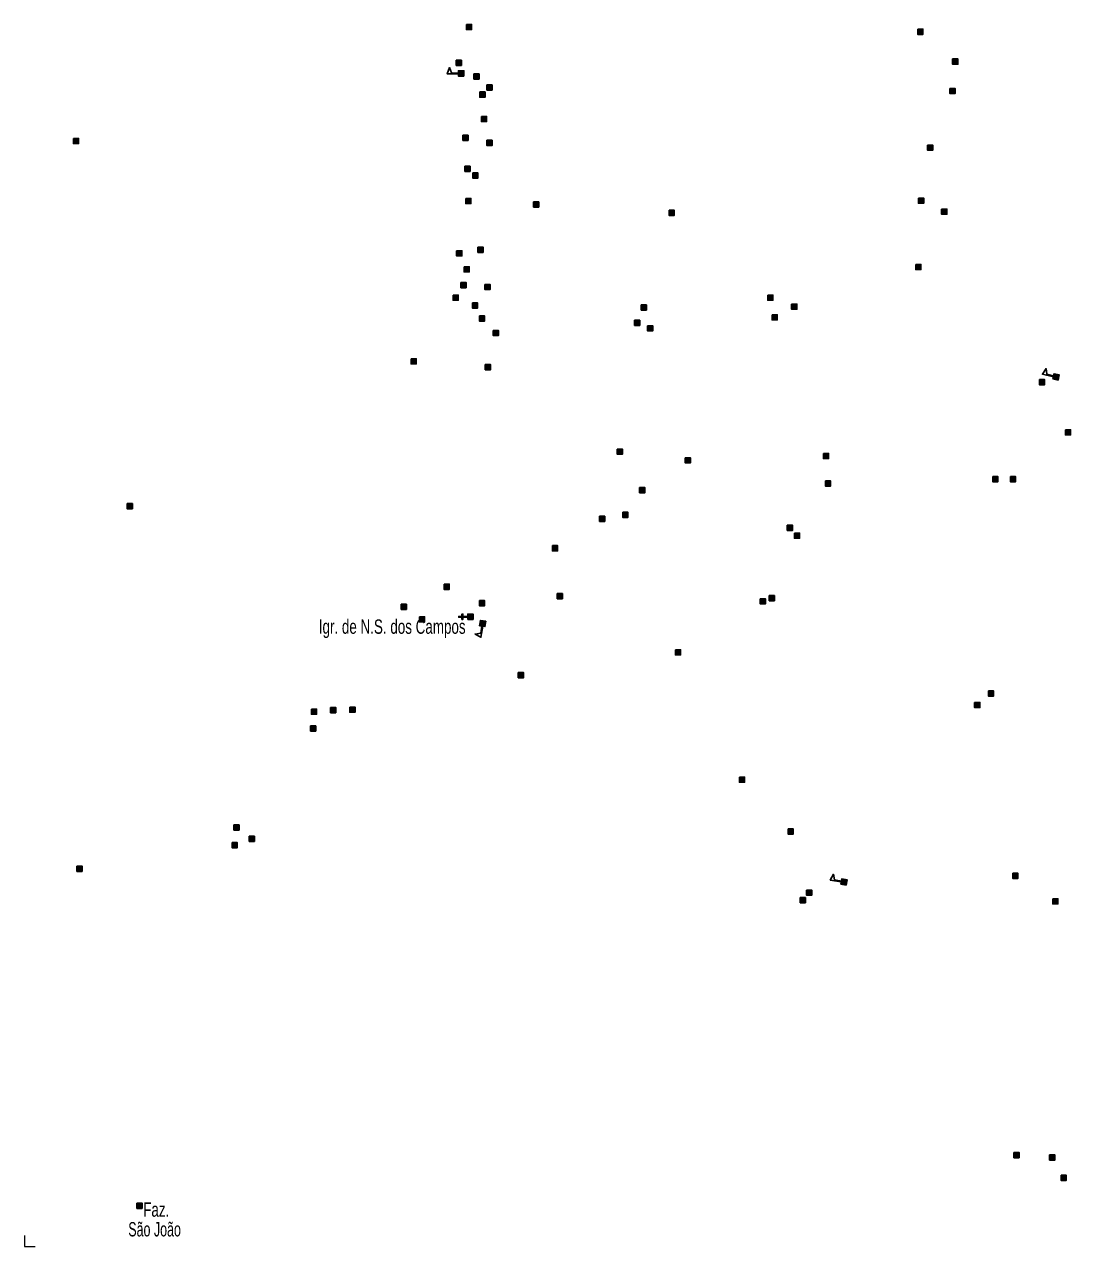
# Model space of a CAD drawing. Extents: x 647.8 to 672.9, y 6929.3 to 6957.3.
# Drawn here: x 647.83 to 653.68, y 6929.58 to 6936.4 of the extents above; entities that cross this region are included whole.
import ezdxf
from ezdxf.enums import TextEntityAlignment as Align

# ---------------------------------------------------------------- set-up
doc = ezdxf.new("R2010")
doc.units = 0
doc.header["$LTSCALE"] = 0.032
for name, color, linetype, lineweight in [('2', 7, 'Continuous', 25), ('4', 7, 'Continuous', 25), ('6', 7, 'Continuous', 25), ('63', 7, 'Continuous', 13)]:
    doc.layers.add(name, color=color, linetype=linetype, lineweight=lineweight)
doc.layers.add('61', color=7, linetype='Continuous')

msp = doc.modelspace()

# ---------------------------------------------------------------- hatches: boundary and pattern name
at = {"layer": '2'}
for points in [[(650.3009, 6936.4039), (650.3299, 6936.4039), (650.3299, 6936.3749), (650.3009, 6936.3749)], [(652.8216, 6936.3776), (652.8506, 6936.3776), (652.8506, 6936.3486), (652.8216, 6936.3486)], [(653.0169, 6936.2109), (653.0459, 6936.2109), (653.0459, 6936.1819), (653.0169, 6936.1819)], [(650.244, 6936.2043), (650.273, 6936.2043), (650.273, 6936.1753), (650.244, 6936.1753)], [(650.3426, 6936.1275), (650.3716, 6936.1275), (650.3716, 6936.0985), (650.3426, 6936.0985)], [(650.3755, 6936.0266), (650.4045, 6936.0266), (650.4045, 6935.9976), (650.3755, 6935.9976)], [(650.415, 6936.0661), (650.444, 6936.0661), (650.444, 6936.0371), (650.415, 6936.0371)], [(653.0015, 6936.0463), (653.0305, 6936.0463), (653.0305, 6936.0173), (653.0015, 6936.0173)], [(650.3842, 6935.8906), (650.4132, 6935.8906), (650.4132, 6935.8616), (650.3842, 6935.8616)], [(648.1048, 6935.7677), (648.1338, 6935.7677), (648.1338, 6935.7387), (648.1048, 6935.7387)], [(650.2811, 6935.7853), (650.3101, 6935.7853), (650.3101, 6935.7563), (650.2811, 6935.7563)], [(650.415, 6935.7567), (650.444, 6935.7567), (650.444, 6935.7277), (650.415, 6935.7277)], [(652.8764, 6935.7304), (652.9054, 6935.7304), (652.9054, 6935.7014), (652.8764, 6935.7014)], [(650.2921, 6935.612), (650.3211, 6935.612), (650.3211, 6935.583), (650.2921, 6935.583)], [(650.336, 6935.5747), (650.365, 6935.5747), (650.365, 6935.5457), (650.336, 6935.5457)], [(650.2965, 6935.4321), (650.3255, 6935.4321), (650.3255, 6935.4031), (650.2965, 6935.4031)], [(650.676, 6935.4123), (650.705, 6935.4123), (650.705, 6935.3833), (650.676, 6935.3833)], [(652.826, 6935.4343), (652.855, 6935.4343), (652.855, 6935.4053), (652.826, 6935.4053)], [(651.4329, 6935.3662), (651.4619, 6935.3662), (651.4619, 6935.3372), (651.4329, 6935.3372)], [(652.9554, 6935.3728), (652.9844, 6935.3728), (652.9844, 6935.3438), (652.9554, 6935.3438)], [(650.246, 6935.1403), (650.275, 6935.1403), (650.275, 6935.1113), (650.246, 6935.1113)], [(650.3645, 6935.16), (650.3935, 6935.16), (650.3935, 6935.131), (650.3645, 6935.131)], [(650.2877, 6935.0503), (650.3167, 6935.0503), (650.3167, 6935.0213), (650.2877, 6935.0213)], [(652.8106, 6935.0635), (652.8396, 6935.0635), (652.8396, 6935.0345), (652.8106, 6935.0345)], [(650.2702, 6934.9626), (650.2992, 6934.9626), (650.2992, 6934.9336), (650.2702, 6934.9336)], [(650.404, 6934.9516), (650.433, 6934.9516), (650.433, 6934.9226), (650.404, 6934.9226)], [(650.2263, 6934.8924), (650.2553, 6934.8924), (650.2553, 6934.8634), (650.2263, 6934.8634)], [(650.3338, 6934.8485), (650.3628, 6934.8485), (650.3628, 6934.8195), (650.3338, 6934.8195)], [(651.9835, 6934.8924), (652.0125, 6934.8924), (652.0125, 6934.8634), (651.9835, 6934.8634)], [(652.1174, 6934.8419), (652.1464, 6934.8419), (652.1464, 6934.8129), (652.1174, 6934.8129)], [(650.3733, 6934.7761), (650.4023, 6934.7761), (650.4023, 6934.7471), (650.3733, 6934.7471)], [(651.2771, 6934.8375), (651.3061, 6934.8375), (651.3061, 6934.8085), (651.2771, 6934.8085)], [(652.0077, 6934.7827), (652.0367, 6934.7827), (652.0367, 6934.7537), (652.0077, 6934.7537)], [(651.2398, 6934.752), (651.2688, 6934.752), (651.2688, 6934.723), (651.2398, 6934.723)], [(651.3122, 6934.7213), (651.3412, 6934.7213), (651.3412, 6934.6923), (651.3122, 6934.6923)], [(650.4501, 6934.6949), (650.4791, 6934.6949), (650.4791, 6934.6659), (650.4501, 6934.6659)], [(649.9915, 6934.537), (650.0205, 6934.537), (650.0205, 6934.508), (649.9915, 6934.508)], [(650.4062, 6934.5041), (650.4352, 6934.5041), (650.4352, 6934.4751), (650.4062, 6934.4751)], [(653.5017, 6934.4207), (653.5307, 6934.4207), (653.5307, 6934.3917), (653.5017, 6934.3917)], [(653.6465, 6934.1399), (653.6755, 6934.1399), (653.6755, 6934.1109), (653.6465, 6934.1109)], [(651.1433, 6934.0324), (651.1723, 6934.0324), (651.1723, 6934.0034), (651.1433, 6934.0034)], [(651.5228, 6933.9841), (651.5518, 6933.9841), (651.5518, 6933.9551), (651.5228, 6933.9551)], [(652.2951, 6934.0083), (652.3241, 6934.0083), (652.3241, 6933.9793), (652.2951, 6933.9793)], [(651.2684, 6933.8174), (651.2974, 6933.8174), (651.2974, 6933.7884), (651.2684, 6933.7884)], [(652.306, 6933.8547), (652.335, 6933.8547), (652.335, 6933.8257), (652.306, 6933.8257)], [(653.2406, 6933.8788), (653.2696, 6933.8788), (653.2696, 6933.8498), (653.2406, 6933.8498)], [(653.3393, 6933.8788), (653.3683, 6933.8788), (653.3683, 6933.8498), (653.3393, 6933.8498)], [(648.4054, 6933.7274), (648.4344, 6933.7274), (648.4344, 6933.6984), (648.4054, 6933.6984)], [(651.0446, 6933.6572), (651.0736, 6933.6572), (651.0736, 6933.6282), (651.0446, 6933.6282)], [(651.174, 6933.6792), (651.203, 6933.6792), (651.203, 6933.6502), (651.174, 6933.6502)], [(652.0932, 6933.6068), (652.1222, 6933.6068), (652.1222, 6933.5778), (652.0932, 6933.5778)], [(652.1327, 6933.5629), (652.1617, 6933.5629), (652.1617, 6933.5339), (652.1327, 6933.5339)], [(650.7813, 6933.4927), (650.8103, 6933.4927), (650.8103, 6933.4637), (650.7813, 6933.4637)], [(650.1758, 6933.2777), (650.2048, 6933.2777), (650.2048, 6933.2487), (650.1758, 6933.2487)], [(650.8076, 6933.2251), (650.8366, 6933.2251), (650.8366, 6933.1961), (650.8076, 6933.1961)], [(651.9923, 6933.2141), (652.0213, 6933.2141), (652.0213, 6933.1851), (651.9923, 6933.1851)], [(649.9367, 6933.1658), (649.9657, 6933.1658), (649.9657, 6933.1368), (649.9367, 6933.1368)], [(650.3733, 6933.1856), (650.4023, 6933.1856), (650.4023, 6933.1566), (650.3733, 6933.1566)], [(651.9419, 6933.1965), (651.9709, 6933.1965), (651.9709, 6933.1675), (651.9419, 6933.1675)], [(650.0376, 6933.0956), (650.0666, 6933.0956), (650.0666, 6933.0666), (650.0376, 6933.0666)], [(651.468, 6932.9113), (651.497, 6932.9113), (651.497, 6932.8823), (651.468, 6932.8823)], [(650.5905, 6932.7841), (650.6195, 6932.7841), (650.6195, 6932.7551), (650.5905, 6932.7551)], [(650.5905, 6932.7841), (650.6195, 6932.7841), (650.6195, 6932.7551), (650.5905, 6932.7551)], [(653.2165, 6932.681), (653.2455, 6932.681), (653.2455, 6932.652), (653.2165, 6932.652)], [(649.5418, 6932.5888), (649.5708, 6932.5888), (649.5708, 6932.5598), (649.5418, 6932.5598)], [(649.6493, 6932.591), (649.6783, 6932.591), (649.6783, 6932.562), (649.6493, 6932.562)], [(653.1397, 6932.6174), (653.1687, 6932.6174), (653.1687, 6932.5884), (653.1397, 6932.5884)], [(649.4343, 6932.5801), (649.4633, 6932.5801), (649.4633, 6932.5511), (649.4343, 6932.5511)], [(649.4299, 6932.4857), (649.4589, 6932.4857), (649.4589, 6932.4567), (649.4299, 6932.4567)], [(651.8256, 6932.2005), (651.8546, 6932.2005), (651.8546, 6932.1715), (651.8256, 6932.1715)], [(649.0021, 6931.9329), (649.0311, 6931.9329), (649.0311, 6931.9039), (649.0021, 6931.9039)], [(652.0976, 6931.9109), (652.1266, 6931.9109), (652.1266, 6931.8819), (652.0976, 6931.8819)], [(649.0877, 6931.8693), (649.1167, 6931.8693), (649.1167, 6931.8403), (649.0877, 6931.8403)], [(648.9911, 6931.8342), (649.0201, 6931.8342), (649.0201, 6931.8052), (648.9911, 6931.8052)], [(648.1246, 6931.7025), (648.1536, 6931.7025), (648.1536, 6931.6735), (648.1246, 6931.6735)], [(653.3525, 6931.663), (653.3815, 6931.663), (653.3815, 6931.634), (653.3525, 6931.634)], [(652.2007, 6931.5687), (652.2297, 6931.5687), (652.2297, 6931.5397), (652.2007, 6931.5397)], [(652.1656, 6931.527), (652.1946, 6931.527), (652.1946, 6931.498), (652.1656, 6931.498)], [(653.5763, 6931.5204), (653.6053, 6931.5204), (653.6053, 6931.4914), (653.5763, 6931.4914)], [(653.3591, 6930.1032), (653.3881, 6930.1032), (653.3881, 6930.0742), (653.3591, 6930.0742)], [(653.5587, 6930.09), (653.5877, 6930.09), (653.5877, 6930.061), (653.5587, 6930.061)], [(653.6224, 6929.976), (653.6514, 6929.976), (653.6514, 6929.947), (653.6224, 6929.947)], [(648.4602, 6929.8202), (648.4892, 6929.8202), (648.4892, 6929.7912), (648.4602, 6929.7912)]]:
    msp.add_hatch(color=256, dxfattribs=at).paths.add_polyline_path(points)
at = {"layer": '4'}
for points in [[(650.2862, 6936.1151), (650.2562, 6936.1151), (650.2562, 6936.1451), (650.2862, 6936.1451)], [(653.6057, 6934.4168), (653.5765, 6934.4237), (653.5834, 6934.4529), (653.6126, 6934.446)], [(650.4086, 6933.0704), (650.4039, 6933.0408), (650.3743, 6933.0455), (650.379, 6933.0751)], [(652.4218, 6931.5968), (652.3922, 6931.6021), (652.3974, 6931.6316), (652.427, 6931.6264)]]:
    msp.add_hatch(color=256, dxfattribs=at).paths.add_polyline_path(points)
at = {"layer": '6'}
for points in [[(650.3082, 6933.0979), (650.3081, 6933.0929), (650.2806, 6933.0929), (650.2807, 6933.0804), (650.2757, 6933.0804), (650.2756, 6933.0929), (650.2581, 6933.0929), (650.2581, 6933.0979), (650.2756, 6933.0979), (650.2756, 6933.1104), (650.2806, 6933.1104), (650.2806, 6933.0979)], [(650.3082, 6933.0805), (650.3381, 6933.0804), (650.3381, 6933.1105), (650.3081, 6933.1104)]]:
    msp.add_hatch(color=256, dxfattribs=at).paths.add_polyline_path(points)

# ---------------------------------------------------------------- linework, layer by layer
at = {"layer": '2'}
for points in [[(650.3009, 6936.4039), (650.3299, 6936.4039), (650.3299, 6936.3749), (650.3009, 6936.3749)], [(652.8216, 6936.3776), (652.8506, 6936.3776), (652.8506, 6936.3486), (652.8216, 6936.3486)], [(653.0169, 6936.2109), (653.0459, 6936.2109), (653.0459, 6936.1819), (653.0169, 6936.1819)], [(650.244, 6936.2043), (650.273, 6936.2043), (650.273, 6936.1753), (650.244, 6936.1753)], [(650.3426, 6936.1275), (650.3716, 6936.1275), (650.3716, 6936.0985), (650.3426, 6936.0985)], [(650.3755, 6936.0266), (650.4045, 6936.0266), (650.4045, 6935.9976), (650.3755, 6935.9976)], [(650.415, 6936.0661), (650.444, 6936.0661), (650.444, 6936.0371), (650.415, 6936.0371)], [(653.0015, 6936.0463), (653.0305, 6936.0463), (653.0305, 6936.0173), (653.0015, 6936.0173)], [(650.3842, 6935.8906), (650.4132, 6935.8906), (650.4132, 6935.8616), (650.3842, 6935.8616)], [(648.1048, 6935.7677), (648.1338, 6935.7677), (648.1338, 6935.7387), (648.1048, 6935.7387)], [(650.2811, 6935.7853), (650.3101, 6935.7853), (650.3101, 6935.7563), (650.2811, 6935.7563)], [(650.415, 6935.7567), (650.444, 6935.7567), (650.444, 6935.7277), (650.415, 6935.7277)], [(652.8764, 6935.7304), (652.9054, 6935.7304), (652.9054, 6935.7014), (652.8764, 6935.7014)], [(650.2921, 6935.612), (650.3211, 6935.612), (650.3211, 6935.583), (650.2921, 6935.583)], [(650.336, 6935.5747), (650.365, 6935.5747), (650.365, 6935.5457), (650.336, 6935.5457)], [(650.2965, 6935.4321), (650.3255, 6935.4321), (650.3255, 6935.4031), (650.2965, 6935.4031)], [(650.676, 6935.4123), (650.705, 6935.4123), (650.705, 6935.3833), (650.676, 6935.3833)], [(652.826, 6935.4343), (652.855, 6935.4343), (652.855, 6935.4053), (652.826, 6935.4053)], [(651.4329, 6935.3662), (651.4619, 6935.3662), (651.4619, 6935.3372), (651.4329, 6935.3372)], [(652.9554, 6935.3728), (652.9844, 6935.3728), (652.9844, 6935.3438), (652.9554, 6935.3438)], [(650.246, 6935.1403), (650.275, 6935.1403), (650.275, 6935.1113), (650.246, 6935.1113)], [(650.3645, 6935.16), (650.3935, 6935.16), (650.3935, 6935.131), (650.3645, 6935.131)], [(650.2877, 6935.0503), (650.3167, 6935.0503), (650.3167, 6935.0213), (650.2877, 6935.0213)], [(652.8106, 6935.0635), (652.8396, 6935.0635), (652.8396, 6935.0345), (652.8106, 6935.0345)], [(650.2702, 6934.9626), (650.2992, 6934.9626), (650.2992, 6934.9336), (650.2702, 6934.9336)], [(650.404, 6934.9516), (650.433, 6934.9516), (650.433, 6934.9226), (650.404, 6934.9226)], [(650.2263, 6934.8924), (650.2553, 6934.8924), (650.2553, 6934.8634), (650.2263, 6934.8634)], [(650.3338, 6934.8485), (650.3628, 6934.8485), (650.3628, 6934.8195), (650.3338, 6934.8195)], [(651.9835, 6934.8924), (652.0125, 6934.8924), (652.0125, 6934.8634), (651.9835, 6934.8634)], [(652.1174, 6934.8419), (652.1464, 6934.8419), (652.1464, 6934.8129), (652.1174, 6934.8129)], [(650.3733, 6934.7761), (650.4023, 6934.7761), (650.4023, 6934.7471), (650.3733, 6934.7471)], [(651.2771, 6934.8375), (651.3061, 6934.8375), (651.3061, 6934.8085), (651.2771, 6934.8085)], [(652.0077, 6934.7827), (652.0367, 6934.7827), (652.0367, 6934.7537), (652.0077, 6934.7537)], [(651.2398, 6934.752), (651.2688, 6934.752), (651.2688, 6934.723), (651.2398, 6934.723)], [(651.3122, 6934.7213), (651.3412, 6934.7213), (651.3412, 6934.6923), (651.3122, 6934.6923)], [(650.4501, 6934.6949), (650.4791, 6934.6949), (650.4791, 6934.6659), (650.4501, 6934.6659)], [(649.9915, 6934.537), (650.0205, 6934.537), (650.0205, 6934.508), (649.9915, 6934.508)], [(650.4062, 6934.5041), (650.4352, 6934.5041), (650.4352, 6934.4751), (650.4062, 6934.4751)], [(653.5017, 6934.4207), (653.5307, 6934.4207), (653.5307, 6934.3917), (653.5017, 6934.3917)], [(653.6465, 6934.1399), (653.6755, 6934.1399), (653.6755, 6934.1109), (653.6465, 6934.1109)], [(651.1433, 6934.0324), (651.1723, 6934.0324), (651.1723, 6934.0034), (651.1433, 6934.0034)], [(651.5228, 6933.9841), (651.5518, 6933.9841), (651.5518, 6933.9551), (651.5228, 6933.9551)], [(652.2951, 6934.0083), (652.3241, 6934.0083), (652.3241, 6933.9793), (652.2951, 6933.9793)], [(651.2684, 6933.8174), (651.2974, 6933.8174), (651.2974, 6933.7884), (651.2684, 6933.7884)], [(652.306, 6933.8547), (652.335, 6933.8547), (652.335, 6933.8257), (652.306, 6933.8257)], [(653.2406, 6933.8788), (653.2696, 6933.8788), (653.2696, 6933.8498), (653.2406, 6933.8498)], [(653.3393, 6933.8788), (653.3683, 6933.8788), (653.3683, 6933.8498), (653.3393, 6933.8498)], [(648.4054, 6933.7274), (648.4344, 6933.7274), (648.4344, 6933.6984), (648.4054, 6933.6984)], [(651.0446, 6933.6572), (651.0736, 6933.6572), (651.0736, 6933.6282), (651.0446, 6933.6282)], [(651.174, 6933.6792), (651.203, 6933.6792), (651.203, 6933.6502), (651.174, 6933.6502)], [(652.0932, 6933.6068), (652.1222, 6933.6068), (652.1222, 6933.5778), (652.0932, 6933.5778)], [(652.1327, 6933.5629), (652.1617, 6933.5629), (652.1617, 6933.5339), (652.1327, 6933.5339)], [(650.7813, 6933.4927), (650.8103, 6933.4927), (650.8103, 6933.4637), (650.7813, 6933.4637)], [(650.1758, 6933.2777), (650.2048, 6933.2777), (650.2048, 6933.2487), (650.1758, 6933.2487)], [(650.8076, 6933.2251), (650.8366, 6933.2251), (650.8366, 6933.1961), (650.8076, 6933.1961)], [(651.9923, 6933.2141), (652.0213, 6933.2141), (652.0213, 6933.1851), (651.9923, 6933.1851)], [(649.9367, 6933.1658), (649.9657, 6933.1658), (649.9657, 6933.1368), (649.9367, 6933.1368)], [(650.3733, 6933.1856), (650.4023, 6933.1856), (650.4023, 6933.1566), (650.3733, 6933.1566)], [(651.9419, 6933.1965), (651.9709, 6933.1965), (651.9709, 6933.1675), (651.9419, 6933.1675)], [(650.0376, 6933.0956), (650.0666, 6933.0956), (650.0666, 6933.0666), (650.0376, 6933.0666)], [(651.468, 6932.9113), (651.497, 6932.9113), (651.497, 6932.8823), (651.468, 6932.8823)], [(650.5905, 6932.7841), (650.6195, 6932.7841), (650.6195, 6932.7551), (650.5905, 6932.7551)], [(650.5905, 6932.7841), (650.6195, 6932.7841), (650.6195, 6932.7551), (650.5905, 6932.7551)], [(653.2165, 6932.681), (653.2455, 6932.681), (653.2455, 6932.652), (653.2165, 6932.652)], [(649.5418, 6932.5888), (649.5708, 6932.5888), (649.5708, 6932.5598), (649.5418, 6932.5598)], [(649.6493, 6932.591), (649.6783, 6932.591), (649.6783, 6932.562), (649.6493, 6932.562)], [(653.1397, 6932.6174), (653.1687, 6932.6174), (653.1687, 6932.5884), (653.1397, 6932.5884)], [(649.4343, 6932.5801), (649.4633, 6932.5801), (649.4633, 6932.5511), (649.4343, 6932.5511)], [(649.4299, 6932.4857), (649.4589, 6932.4857), (649.4589, 6932.4567), (649.4299, 6932.4567)], [(651.8256, 6932.2005), (651.8546, 6932.2005), (651.8546, 6932.1715), (651.8256, 6932.1715)], [(649.0021, 6931.9329), (649.0311, 6931.9329), (649.0311, 6931.9039), (649.0021, 6931.9039)], [(652.0976, 6931.9109), (652.1266, 6931.9109), (652.1266, 6931.8819), (652.0976, 6931.8819)], [(649.0877, 6931.8693), (649.1167, 6931.8693), (649.1167, 6931.8403), (649.0877, 6931.8403)], [(648.9911, 6931.8342), (649.0201, 6931.8342), (649.0201, 6931.8052), (648.9911, 6931.8052)], [(648.1246, 6931.7025), (648.1536, 6931.7025), (648.1536, 6931.6735), (648.1246, 6931.6735)], [(653.3525, 6931.663), (653.3815, 6931.663), (653.3815, 6931.634), (653.3525, 6931.634)], [(652.2007, 6931.5687), (652.2297, 6931.5687), (652.2297, 6931.5397), (652.2007, 6931.5397)], [(652.1656, 6931.527), (652.1946, 6931.527), (652.1946, 6931.498), (652.1656, 6931.498)], [(653.5763, 6931.5204), (653.6053, 6931.5204), (653.6053, 6931.4914), (653.5763, 6931.4914)], [(653.3591, 6930.1032), (653.3881, 6930.1032), (653.3881, 6930.0742), (653.3591, 6930.0742)], [(653.5587, 6930.09), (653.5877, 6930.09), (653.5877, 6930.061), (653.5587, 6930.061)], [(653.6224, 6929.976), (653.6514, 6929.976), (653.6514, 6929.947), (653.6224, 6929.947)], [(648.4602, 6929.8202), (648.4892, 6929.8202), (648.4892, 6929.7912), (648.4602, 6929.7912)]]:
    msp.add_lwpolyline(points, close=True, dxfattribs=at)
at = {"layer": '4'}
for p, q in [((650.2562, 6936.1276), (650.2562, 6936.1326)), ((653.5794, 6934.4359), (653.5805, 6934.4407)), ((650.3916, 6933.0428), (650.3866, 6933.0435)), ((652.3945, 6931.6144), (652.3953, 6931.6193))]:
    msp.add_line(p, q, dxfattribs=at)
for points in [[(650.2562, 6936.1276), (650.1937, 6936.1277), (650.2063, 6936.1627), (650.2167, 6936.1327), (650.2562, 6936.1326)], [(650.2862, 6936.1151), (650.2562, 6936.1151), (650.2562, 6936.1451), (650.2862, 6936.1451)], [(653.5794, 6934.4359), (653.5185, 6934.4501), (653.5387, 6934.4813), (653.5421, 6934.4497), (653.5805, 6934.4407)], [(653.6057, 6934.4168), (653.5765, 6934.4237), (653.5834, 6934.4529), (653.6126, 6934.446)], [(650.4086, 6933.0704), (650.4039, 6933.0408), (650.3743, 6933.0455), (650.379, 6933.0751)], [(650.3916, 6933.0428), (650.3817, 6932.981), (650.3491, 6932.9989), (650.3804, 6933.0045), (650.3866, 6933.0435)], [(652.3945, 6931.6144), (652.3328, 6931.6252), (652.3512, 6931.6575), (652.3564, 6931.6262), (652.3953, 6931.6193)], [(652.4218, 6931.5968), (652.3922, 6931.6021), (652.3974, 6931.6316), (652.427, 6931.6264)]]:
    msp.add_lwpolyline(points, close=True, dxfattribs=at)
at = {"layer": '6'}
for points in [[(650.3082, 6933.0979), (650.3081, 6933.0929), (650.2806, 6933.0929), (650.2807, 6933.0804), (650.2757, 6933.0804), (650.2756, 6933.0929), (650.2581, 6933.0929), (650.2581, 6933.0979), (650.2756, 6933.0979), (650.2756, 6933.1104), (650.2806, 6933.1104), (650.2806, 6933.0979)], [(650.3082, 6933.0805), (650.3381, 6933.0804), (650.3381, 6933.1105), (650.3081, 6933.1104)]]:
    msp.add_lwpolyline(points, close=True, dxfattribs=at)
at = {"layer": '63'}
msp.add_lwpolyline([(647.8316, 6929.6394), (647.8316, 6929.5778), (647.8923, 6929.5778)], dxfattribs=at)

# ---------------------------------------------------------------- texts
at = {"layer": '61', "width": 0.7}
msp.add_text('Igr. de N.S. dos Campos', height=0.08, dxfattribs=at).set_placement((650.296, 6933.0004), align=Align.RIGHT)
at = {"layer": '61'}
for s, width, p in [('    Faz.', 0.7, (648.4118, 6929.7443)), ('São João', 0.65, (648.4118, 6929.6343))]:
    msp.add_text(s, height=0.08, dxfattribs=dict(at, width=width)).set_placement(p)

doc.saveas('drawing.dxf')
